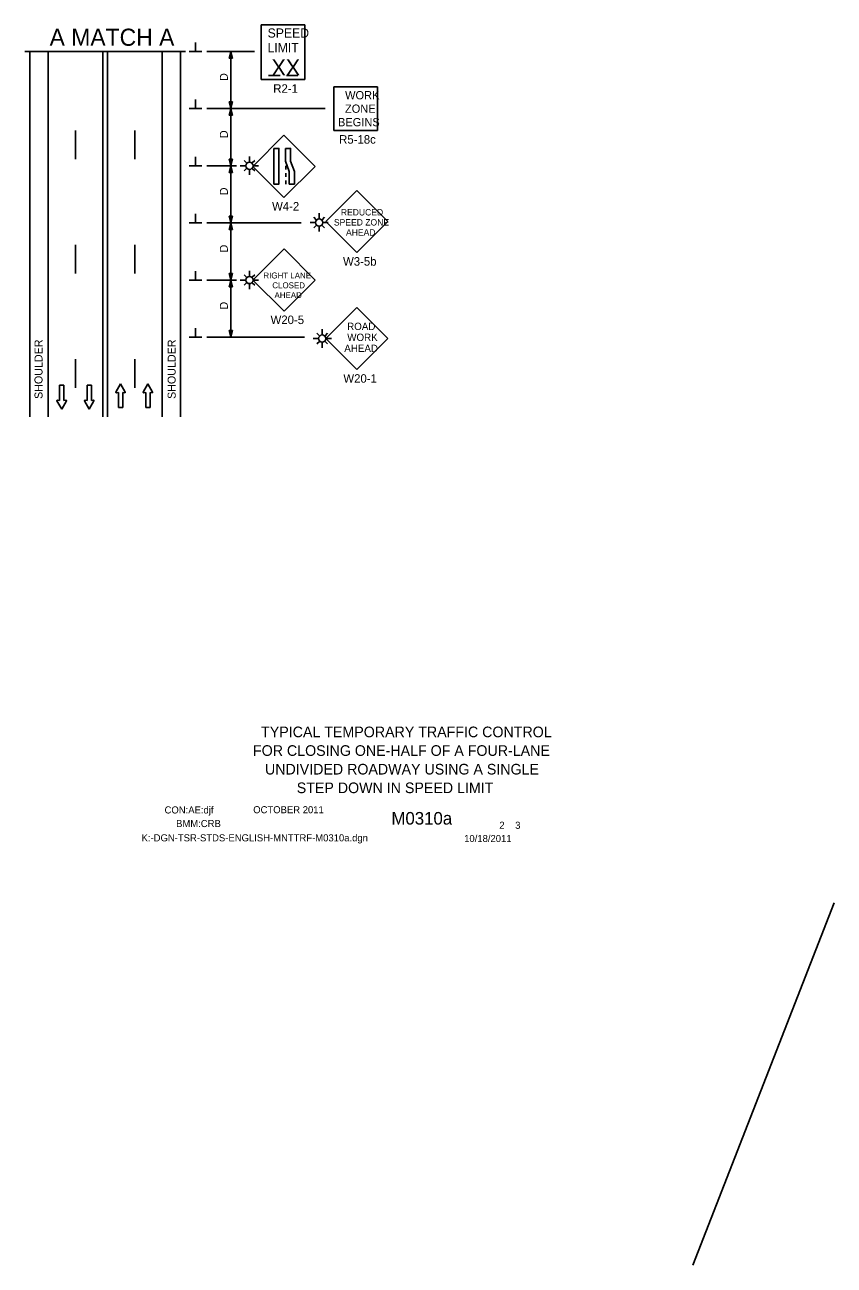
# Model space of a CAD drawing. Extents: x 16473 to 19504, y 4850 to 6919.
# Drawn here: x 17997 to 18706, y 5563 to 6648 of the extents above; entities that cross this region are included whole.
import ezdxf

# ---------------------------------------------------------------- set-up
doc = ezdxf.new("R2010")
doc.units = 0
for name, color, linetype in [('ALI_LEGAL_EX', 7, 'Continuous'), ('BORDER_SIGNAL_WO', 7, 'Continuous'), ('MT_SCRATCH_LEVEL_E', 7, 'Continuous'), ('PAVT_EDGE_EX', 7, 'Continuous'), ('TRAFFIC_SIGNS_PR', 7, 'Continuous'), ('TYPICAL_TEXT_DIMEN_PR', 7, 'Continuous')]:
    doc.layers.add(name, color=color, linetype=linetype)

msp = doc.modelspace()

# ---------------------------------------------------------------- linework, layer by layer
at = {"layer": 'ALI_LEGAL_EX'}
for points in [[(18041.7, 6555.4), (18041.7, 6530.4)], [(18093.7, 6555.4), (18093.7, 6530.4)], [(18041.7, 6455.4), (18041.7, 6430.4)], [(18093.7, 6455.4), (18093.7, 6430.4)], [(18041.7, 6355.4), (18041.7, 6330.4)], [(18093.7, 6355.4), (18093.7, 6330.4)]]:
    msp.add_lwpolyline(points, dxfattribs=at)
at = {"layer": 'MT_SCRATCH_LEVEL_E'}
for p, q in [((18031.5, 6332.7), (18027.8, 6332.7)), ((18027.8, 6332.7), (18027.8, 6319.4)), ((18031.5, 6332.7), (18027.8, 6332.7)), ((18027.8, 6332.7), (18027.8, 6319.4)), ((18031.5, 6319.4), (18031.5, 6332.7)), ((18031.5, 6319.4), (18031.5, 6332.7)), ((18055.7, 6332.7), (18051.9, 6332.7)), ((18051.9, 6332.7), (18051.9, 6319.4)), ((18055.7, 6332.7), (18051.9, 6332.7)), ((18051.9, 6332.7), (18051.9, 6319.4)), ((18055.7, 6319.4), (18055.7, 6332.7)), ((18055.7, 6319.4), (18055.7, 6332.7)), ((18081.2, 6333.9), (18077.1, 6326.7)), ((18081.2, 6333.9), (18077.1, 6326.7)), ((18077.5, 6326), (18079.3, 6326.3)), ((18077.5, 6326), (18079.3, 6326.3)), ((18079.3, 6326.3), (18079.3, 6313.1)), ((18079.3, 6326.3), (18079.3, 6313.1)), ((18085.3, 6326.7), (18081.2, 6333.9)), ((18085.3, 6326.7), (18081.2, 6333.9)), ((18083.1, 6313.1), (18083.1, 6326.3)), ((18083.1, 6326.3), (18084.8, 6326)), ((18083.1, 6313.1), (18083.1, 6326.3)), ((18083.1, 6326.3), (18084.8, 6326)), ((18105.1, 6333.9), (18101, 6326.7)), ((18105.1, 6333.9), (18101, 6326.7)), ((18101.5, 6326), (18103.3, 6326.3)), ((18101.5, 6326), (18103.3, 6326.3)), ((18103.3, 6326.3), (18103.3, 6313.1)), ((18103.3, 6326.3), (18103.3, 6313.1)), ((18109.2, 6326.7), (18105.1, 6333.9)), ((18109.2, 6326.7), (18105.1, 6333.9)), ((18107, 6313.1), (18107, 6326.3)), ((18107, 6326.3), (18108.8, 6326)), ((18107, 6313.1), (18107, 6326.3)), ((18107, 6326.3), (18108.8, 6326)), ((18025.5, 6319), (18029.7, 6311.8)), ((18025.5, 6319), (18029.7, 6311.8)), ((18027.8, 6319.4), (18026, 6319.7)), ((18027.8, 6319.4), (18026, 6319.7)), ((18029.7, 6311.8), (18033.8, 6319)), ((18029.7, 6311.8), (18033.8, 6319)), ((18033.3, 6319.7), (18031.5, 6319.4)), ((18033.3, 6319.7), (18031.5, 6319.4)), ((18049.7, 6319), (18053.8, 6311.8)), ((18049.7, 6319), (18053.8, 6311.8)), ((18051.9, 6319.4), (18050.2, 6319.7)), ((18051.9, 6319.4), (18050.2, 6319.7)), ((18053.8, 6311.8), (18057.9, 6319)), ((18053.8, 6311.8), (18057.9, 6319)), ((18057.5, 6319.7), (18055.7, 6319.4)), ((18057.5, 6319.7), (18055.7, 6319.4)), ((18079.3, 6313.1), (18083.1, 6313.1)), ((18079.3, 6313.1), (18083.1, 6313.1)), ((18103.3, 6313.1), (18107, 6313.1)), ((18103.3, 6313.1), (18107, 6313.1))]:
    msp.add_line(p, q, dxfattribs=at)
for centre, start, end in [((18077.5, 6326.5), 150.4248, 279.9638), ((18077.5, 6326.5), 150.4248, 279.9638), ((18084.9, 6326.5), 260.0362, 29.7731), ((18084.9, 6326.5), 260.0362, 29.7731), ((18101.4, 6326.5), 150.4248, 279.9638), ((18101.4, 6326.5), 150.4248, 279.9638), ((18108.8, 6326.5), 260.0362, 29.7731), ((18108.8, 6326.5), 260.0362, 29.7731), ((18025.9, 6319.2), 80.0362, 209.7731), ((18025.9, 6319.2), 80.0362, 209.7731), ((18033.4, 6319.2), 330.4248, 99.9638), ((18033.4, 6319.2), 330.4248, 99.9638), ((18050.1, 6319.2), 80.0362, 209.7731), ((18050.1, 6319.2), 80.0362, 209.7731), ((18057.5, 6319.2), 330.4248, 99.9638), ((18057.5, 6319.2), 330.4248, 99.9638)]:
    msp.add_arc(centre, 0.463, start, end, dxfattribs=at)
at = {"layer": 'PAVT_EDGE_EX'}
for p, q in [((18001.7, 6624.7), (18001.7, 6305.2)), ((18017.7, 6624.7), (18017.7, 6305.2)), ((18065.7, 6624.7), (18065.7, 6305.2)), ((18069.7, 6624.7), (18069.7, 6305.2)), ((18117.7, 6624.7), (18117.7, 6305.2)), ((18133.7, 6624.7), (18133.7, 6305.2))]:
    msp.add_line(p, q, dxfattribs=at)
at = {"layer": 'TRAFFIC_SIGNS_PR'}
for p, q in [((18204.2, 6648), (18242.6, 6648)), ((18204.2, 6600), (18204.2, 6648)), ((18204.2, 6648), (18242.6, 6648)), ((18204.2, 6600), (18204.2, 6648)), ((18242.6, 6600), (18242.6, 6648)), ((18242.6, 6600), (18242.6, 6648)), ((18204.2, 6600), (18242.6, 6600)), ((18204.2, 6600), (18242.6, 6600)), ((18210.8, 6603.6), (18220.9, 6603.6)), ((18226.3, 6603.6), (18236.3, 6603.6)), ((18267.7, 6555.4), (18267.7, 6593.8)), ((18267.7, 6593.8), (18306.1, 6593.8)), ((18306.1, 6555.4), (18306.1, 6593.8)), ((18267.7, 6555.4), (18306.1, 6555.4)), ((18224.2, 6551.3), (18197.1, 6524.1)), ((18251.4, 6524.1), (18224.2, 6551.3)), ((18194, 6528.3), (18194, 6532.8)), ((18190.8, 6524.7), (18186, 6524.7)), ((18191.5, 6527.2), (18189.4, 6529.3)), ((18191.5, 6522.2), (18189.4, 6520.1)), ((18194, 6516.8), (18194, 6521.2)), ((18196.5, 6527.2), (18198.6, 6529.3)), ((18196.5, 6522.2), (18198.6, 6520.1)), ((18197.1, 6524.7), (18202, 6524.7)), ((18197.1, 6524.1), (18224.2, 6497)), ((18224.2, 6497), (18251.4, 6524.1)), ((18225.9, 6524.6), (18225.9, 6521.4)), ((18225.9, 6518.2), (18225.9, 6515)), ((18225.9, 6511.8), (18225.9, 6508.6)), ((18287.9, 6503), (18260.7, 6475.9)), ((18315, 6475.9), (18287.9, 6503)), ((18252.5, 6477.5), (18250.4, 6479.6)), ((18255, 6478.6), (18255, 6483.1)), ((18257.5, 6477.5), (18259.6, 6479.6)), ((18251.9, 6475), (18247, 6475)), ((18252.5, 6472.5), (18250.4, 6470.4)), ((18255, 6467.1), (18255, 6471.5)), ((18257.5, 6472.5), (18259.6, 6470.4)), ((18258.2, 6475), (18263, 6475)), ((18260.7, 6475.9), (18287.9, 6448.7)), ((18287.9, 6448.7), (18315, 6475.9)), ((18224.3, 6451.9), (18197.1, 6424.7)), ((18251.4, 6424.7), (18224.3, 6451.9)), ((18190.8, 6424.7), (18186, 6424.7)), ((18191.5, 6427.3), (18189.4, 6429.4)), ((18194, 6428.3), (18194, 6432.8)), ((18196.5, 6427.3), (18198.6, 6429.4)), ((18197.1, 6424.7), (18202, 6424.7)), ((18197.1, 6424.7), (18224.3, 6397.6)), ((18224.3, 6397.6), (18251.4, 6424.7)), ((18191.5, 6422.2), (18189.4, 6420.1)), ((18194, 6416.8), (18194, 6421.2)), ((18196.5, 6422.2), (18198.6, 6420.1)), ((18288, 6400.7), (18260.8, 6373.5)), ((18315.1, 6373.5), (18288, 6400.7)), ((18257.7, 6377.1), (18257.7, 6381.6)), ((18254.5, 6373.5), (18249.7, 6373.5)), ((18255.2, 6376), (18253.1, 6378.1)), ((18255.2, 6371), (18253.1, 6368.9)), ((18257.7, 6365.5), (18257.7, 6370)), ((18260.2, 6376), (18262.3, 6378.1)), ((18260.2, 6371), (18262.3, 6368.9)), ((18260.8, 6373.5), (18288, 6346.4)), ((18260.8, 6373.5), (18265.7, 6373.5)), ((18288, 6346.4), (18315.1, 6373.5))]:
    msp.add_line(p, q, dxfattribs=at)
for points in [[(18215.4, 6539.9), (18215.4, 6508.6), (18219.8, 6508.6), (18219.8, 6539.9)], [(18225.5, 6539.9), (18225.5, 6528.7), (18228.8, 6519.8), (18228.8, 6508.6), (18233.3, 6508.6), (18233.3, 6519.8), (18230, 6528.7), (18230, 6539.9)]]:
    msp.add_lwpolyline(points, close=True, dxfattribs=at)
for centre in [(18194, 6524.7), (18255, 6475), (18194, 6424.7), (18257.7, 6373.5)]:
    msp.add_circle(centre, 3.15, dxfattribs=at)
at = {"layer": 'TYPICAL_TEXT_DIMEN_PR'}
for p, q in [((18146.8, 6624.7), (18146.8, 6632.5)), ((17997.4, 6624.7), (18138, 6624.7)), ((18152.4, 6624.7), (18141.2, 6624.7)), ((18198.3, 6624.7), (18156.7, 6624.7)), ((18176.1, 6618.8), (18177.7, 6624.7)), ((18177.7, 6618.8), (18176.1, 6618.8)), ((18177.7, 6624.7), (18177.7, 6574.7)), ((18177.7, 6624.7), (18179.3, 6618.8)), ((18179.3, 6618.8), (18177.7, 6618.8)), ((18146.8, 6574.7), (18146.8, 6582.5)), ((18177.7, 6574.7), (18176.1, 6580.5)), ((18176.1, 6580.5), (18177.7, 6580.5)), ((18177.7, 6580.5), (18179.3, 6580.5)), ((18179.3, 6580.5), (18177.7, 6574.7)), ((18152.4, 6574.7), (18141.2, 6574.7)), ((18260.3, 6574.7), (18156.7, 6574.7)), ((18176.1, 6568.8), (18177.7, 6574.7)), ((18177.7, 6568.8), (18176.1, 6568.8)), ((18177.7, 6574.7), (18179.3, 6568.8)), ((18177.7, 6574.7), (18177.7, 6524.7)), ((18179.3, 6568.8), (18177.7, 6568.8)), ((18146.8, 6524.7), (18146.8, 6532.5)), ((18152.4, 6524.7), (18141.2, 6524.7)), ((18182.7, 6524.7), (18156.7, 6524.7)), ((18177.7, 6524.7), (18176.1, 6530.5)), ((18176.1, 6530.5), (18177.7, 6530.5)), ((18176.1, 6518.8), (18177.7, 6524.7)), ((18177.7, 6530.5), (18179.3, 6530.5)), ((18179.3, 6530.5), (18177.7, 6524.7)), ((18177.7, 6524.7), (18177.7, 6474.7)), ((18177.7, 6524.7), (18179.3, 6518.8)), ((18177.7, 6518.8), (18176.1, 6518.8)), ((18179.3, 6518.8), (18177.7, 6518.8)), ((18146.8, 6474.7), (18146.8, 6482.5)), ((18177.7, 6474.7), (18176.1, 6480.5)), ((18176.1, 6480.5), (18177.7, 6480.5)), ((18177.7, 6480.5), (18179.3, 6480.5)), ((18179.3, 6480.5), (18177.7, 6474.7)), ((18152.4, 6474.7), (18141.2, 6474.7)), ((18239.4, 6474.7), (18156.7, 6474.7)), ((18176.1, 6468.8), (18177.7, 6474.7)), ((18177.7, 6468.8), (18176.1, 6468.8)), ((18177.7, 6474.7), (18177.7, 6424.7)), ((18177.7, 6474.7), (18179.3, 6468.8)), ((18179.3, 6468.8), (18177.7, 6468.8)), ((18152.4, 6424.7), (18141.2, 6424.7)), ((18146.8, 6424.7), (18146.8, 6432.5)), ((18182.7, 6424.7), (18156.7, 6424.7)), ((18177.7, 6424.7), (18176.1, 6430.5)), ((18176.1, 6430.5), (18177.7, 6430.5)), ((18176.1, 6418.8), (18177.7, 6424.7)), ((18177.7, 6430.5), (18179.3, 6430.5)), ((18179.3, 6430.5), (18177.7, 6424.7)), ((18177.7, 6424.7), (18177.7, 6374.7)), ((18177.7, 6424.7), (18179.3, 6418.8)), ((18177.7, 6418.8), (18176.1, 6418.8)), ((18179.3, 6418.8), (18177.7, 6418.8)), ((18146.8, 6374.7), (18146.8, 6382.5)), ((18177.7, 6374.7), (18176.1, 6380.5)), ((18176.1, 6380.5), (18177.7, 6380.5)), ((18177.7, 6380.5), (18179.3, 6380.5)), ((18179.3, 6380.5), (18177.7, 6374.7)), ((18152.4, 6374.7), (18141.2, 6374.7)), ((18242.3, 6374.7), (18156.7, 6374.7)), ((18705.8, 5880), (18582.1, 5563))]:
    msp.add_line(p, q, dxfattribs=at)

# ---------------------------------------------------------------- texts
at = {"layer": 'BORDER_SIGNAL_WO'}
for s, height, p in [('TYPICAL TEMPORARY TRAFFIC CONTROL', 9.3, (18204.2, 6024.8)), ('FOR CLOSING ONE-HALF OF A FOUR-LANE', 9.3, (18197.1, 6008.5)), ('UNDIVIDED ROADWAY USING A SINGLE', 9.3, (18207.6, 5992.2)), ('STEP DOWN IN SPEED LIMIT', 9.3, (18235.4, 5975.9)), ('CON:AE:djf', 6.2, (18119.7, 5958.1)), ('    OCTOBER 2011    ', 6.2, (18188.1, 5958.3)), ('    M0310a   ', 11, (18301.9, 5948.4)), ('BMM:CRB   ', 6.2, (18129.8, 5946.2)), (' 2    3 ', 6.2, (18410.4, 5944.7)), ('K:-DGN-TSR-STDS-ENGLISH-MNTTRF-M0310a.dgn        ', 6.2, (18099.6, 5933.7)), ('10/18/2011    ', 6.2, (18381.9, 5933.1))]:
    msp.add_text(s, height=height, dxfattribs=at).set_placement(p)
at = {"layer": 'TRAFFIC_SIGNS_PR'}
for s, height, p in [('SPEED', 8, (18209.9, 6636.8)), ('SPEED', 8, (18209.9, 6636.8)), ('LIMIT', 8, (18209.8, 6624)), ('LIMIT', 8, (18209.8, 6624)), ('XX', 14.03, (18213.3, 6603.7)), ('R2-1', 7.44, (18214.9, 6588.5)), ('R2-1', 7.44, (18214.8, 6588.5)), ('WORK', 7.22, (18277.7, 6582.8)), ('ZONE', 7.22, (18277.6, 6571)), ('BEGINS', 7.22, (18271.5, 6559.2)), ('R5-18c', 7.44, (18272.5, 6544)), ('W4-2', 7.44, (18213.8, 6485.5)), ('SPEED ZONE', 5.6, (18267.9, 6472.4)), ('REDUCED', 5.6, (18274, 6481.2)), ('AHEAD', 5.6, (18278.5, 6463.6)), ('W3-5b', 7.44, (18275.9, 6437.3)), ('RIGHT LANE', 5.2, (18206.2, 6426.1)), ('CLOSED', 5.2, (18214, 6417.5)), ('AHEAD', 5.2, (18215.9, 6408.9)), ('W20-5', 7.44, (18212.5, 6386.2)), ('ROAD', 6.4, (18279.5, 6381)), ('WORK', 6.4, (18279.6, 6371.4)), ('AHEAD', 6.4, (18277, 6361.8)), ('W20-1', 7.44, (18276.2, 6334.9))]:
    msp.add_text(s, height=height, dxfattribs=at).set_placement(p)
at = {"layer": 'TYPICAL_TEXT_DIMEN_PR'}
msp.add_text('A MATCH A', height=15, dxfattribs=at).set_placement((18019.1, 6629.6))
for s, p in [('D', (18175.1, 6598.9)), ('D', (18175.1, 6548.9)), ('D', (18175.1, 6498.9)), ('D', (18175.1, 6448.9)), ('D', (18175.1, 6398.9)), ('SHOULDER', (18012.9, 6320.7)), ('SHOULDER', (18129.4, 6320.7))]:
    msp.add_text(s, height=7, rotation=90, dxfattribs=at).set_placement(p)

doc.saveas('drawing.dxf')
